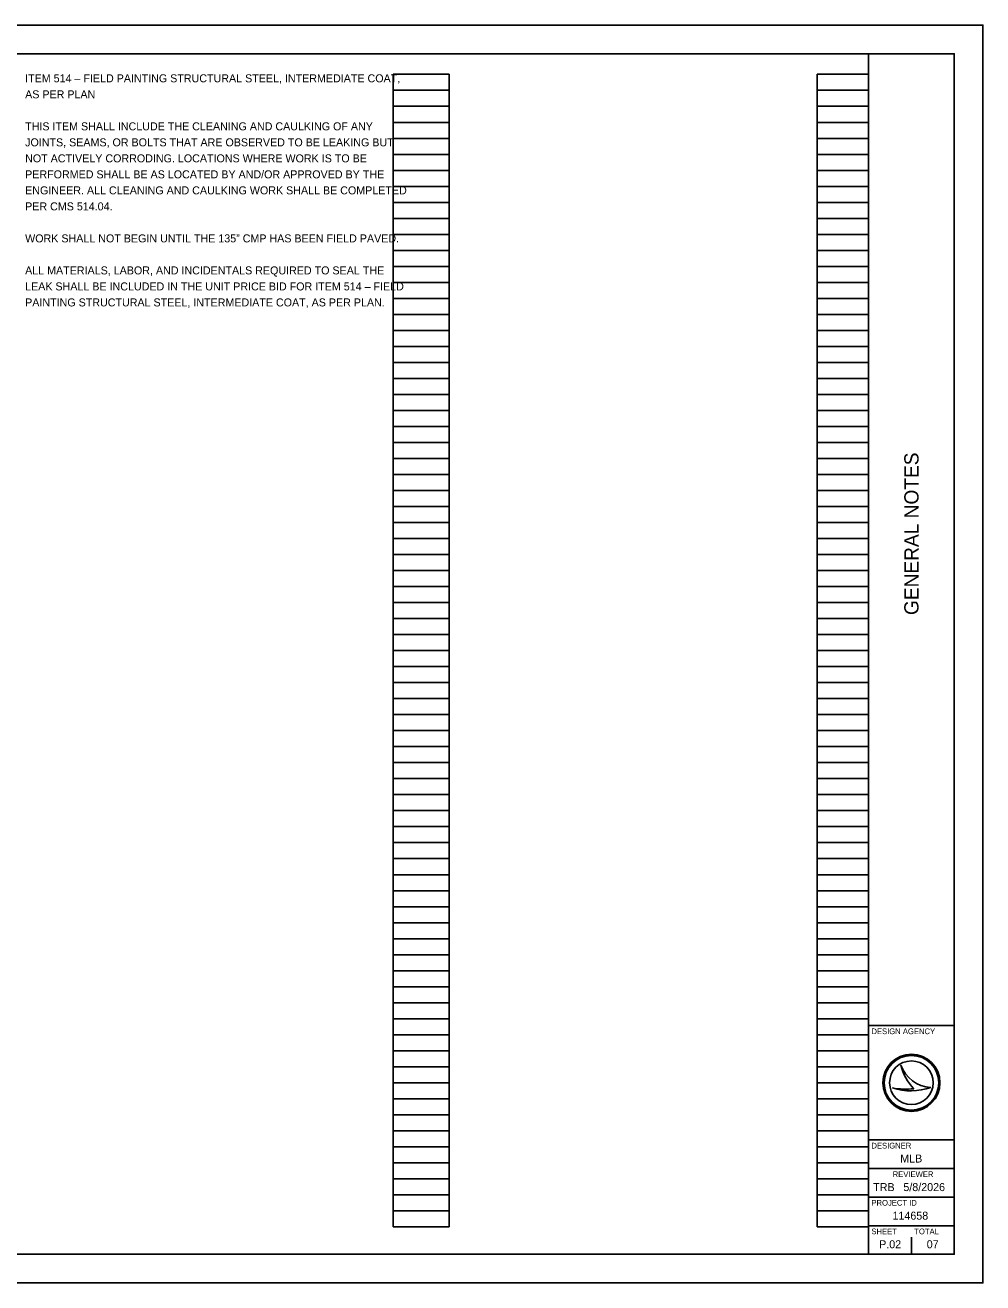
# Model space of a CAD drawing. Extents: x 0 to 34, y 0 to 22.
# Drawn here: x 17.24 to 34, y 0 to 22 of the extents above; entities that cross this region are included whole.
import ezdxf

# ---------------------------------------------------------------- set-up
doc = ezdxf.new("R2010")
doc.units = 0
for name, color, linetype in [('SH_Border', 7, 'Continuous'), ('SH_Cut_Line', 7, 'Continuous'), ('SH_Data', 7, 'Continuous'), ('SH_Text', 7, 'Continuous')]:
    doc.layers.add(name, color=color, linetype=linetype)

msp = doc.modelspace()

# ---------------------------------------------------------------- linework, layer by layer
at = {"layer": 'SH_Border'}
for p, q in [((32, 0.5), (32, 21.5)), ((32, 4.5), (33.5, 4.5)), ((32, 2.5), (33.5, 2.5)), ((32, 2), (33.5, 2)), ((32, 1.5), (33.5, 1.5)), ((32, 1), (33.5, 1))]:
    msp.add_line(p, q, dxfattribs=at)
msp.add_lwpolyline([(1.5, 21.5), (33.5, 21.5), (33.5, 0.5), (1.5, 0.5)], close=True, dxfattribs=at)
at = {"layer": 'SH_Cut_Line'}
msp.add_lwpolyline([(0, 0), (34, 0), (34, 22), (0, 22)], close=True, dxfattribs=at)
at = {"layer": 'SH_Data'}
for p, q in [((23.68, 0.98), (23.68, 21.14)), ((23.68, 21.14), (24.66, 21.14)), ((24.66, 0.98), (24.66, 21.14)), ((31.1, 0.98), (31.1, 21.14)), ((31.1, 21.14), (32, 21.14)), ((32, 0.98), (32, 21.14)), ((23.68, 20.86), (24.66, 20.86)), ((31.1, 20.86), (32, 20.86)), ((23.68, 20.58), (24.66, 20.58)), ((31.1, 20.58), (32, 20.58)), ((23.68, 20.3), (24.66, 20.3)), ((31.1, 20.3), (32, 20.3)), ((23.68, 20.02), (24.66, 20.02)), ((31.1, 20.02), (32, 20.02)), ((23.68, 19.74), (24.66, 19.74)), ((31.1, 19.74), (32, 19.74)), ((23.68, 19.46), (24.66, 19.46)), ((31.1, 19.46), (32, 19.46)), ((23.68, 19.18), (24.66, 19.18)), ((31.1, 19.18), (32, 19.18)), ((23.68, 18.9), (24.66, 18.9)), ((31.1, 18.9), (32, 18.9)), ((23.68, 18.62), (24.66, 18.62)), ((31.1, 18.62), (32, 18.62)), ((23.68, 18.34), (24.66, 18.34)), ((31.1, 18.34), (32, 18.34)), ((23.68, 18.06), (24.66, 18.06)), ((31.1, 18.06), (32, 18.06)), ((23.68, 17.78), (24.66, 17.78)), ((31.1, 17.78), (32, 17.78)), ((23.68, 17.5), (24.66, 17.5)), ((31.1, 17.5), (32, 17.5)), ((23.68, 17.22), (24.66, 17.22)), ((31.1, 17.22), (32, 17.22)), ((23.68, 16.94), (24.66, 16.94)), ((31.1, 16.94), (32, 16.94)), ((23.68, 16.66), (24.66, 16.66)), ((31.1, 16.66), (32, 16.66)), ((23.68, 16.38), (24.66, 16.38)), ((31.1, 16.38), (32, 16.38)), ((23.68, 16.1), (24.66, 16.1)), ((31.1, 16.1), (32, 16.1)), ((23.68, 15.82), (24.66, 15.82)), ((31.1, 15.82), (32, 15.82)), ((23.68, 15.54), (24.66, 15.54)), ((31.1, 15.54), (32, 15.54)), ((23.68, 15.26), (24.66, 15.26)), ((31.1, 15.26), (32, 15.26)), ((23.68, 14.98), (24.66, 14.98)), ((31.1, 14.98), (32, 14.98)), ((23.68, 14.7), (24.66, 14.7)), ((31.1, 14.7), (32, 14.7)), ((23.68, 14.42), (24.66, 14.42)), ((31.1, 14.42), (32, 14.42)), ((23.68, 14.14), (24.66, 14.14)), ((31.1, 14.14), (32, 14.14)), ((23.68, 13.86), (24.66, 13.86)), ((31.1, 13.86), (32, 13.86)), ((23.68, 13.58), (24.66, 13.58)), ((31.1, 13.58), (32, 13.58)), ((23.68, 13.3), (24.66, 13.3)), ((31.1, 13.3), (32, 13.3)), ((23.68, 13.02), (24.66, 13.02)), ((31.1, 13.02), (32, 13.02)), ((23.68, 12.74), (24.66, 12.74)), ((31.1, 12.74), (32, 12.74)), ((23.68, 12.46), (24.66, 12.46)), ((31.1, 12.46), (32, 12.46)), ((23.68, 12.18), (24.66, 12.18)), ((31.1, 12.18), (32, 12.18)), ((23.68, 11.9), (24.66, 11.9)), ((31.1, 11.9), (32, 11.9)), ((23.68, 11.62), (24.66, 11.62)), ((31.1, 11.62), (32, 11.62)), ((23.68, 11.34), (24.66, 11.34)), ((31.1, 11.34), (32, 11.34)), ((23.68, 11.06), (24.66, 11.06)), ((31.1, 11.06), (32, 11.06)), ((23.68, 10.78), (24.66, 10.78)), ((31.1, 10.78), (32, 10.78)), ((23.68, 10.5), (24.66, 10.5)), ((31.1, 10.5), (32, 10.5)), ((23.68, 10.22), (24.66, 10.22)), ((31.1, 10.22), (32, 10.22)), ((23.68, 9.94), (24.66, 9.94)), ((31.1, 9.94), (32, 9.94)), ((23.68, 9.66), (24.66, 9.66)), ((31.1, 9.66), (32, 9.66)), ((23.68, 9.38), (24.66, 9.38)), ((31.1, 9.38), (32, 9.38)), ((23.68, 9.1), (24.66, 9.1)), ((31.1, 9.1), (32, 9.1)), ((23.68, 8.82), (24.66, 8.82)), ((31.1, 8.82), (32, 8.82)), ((23.68, 8.54), (24.66, 8.54)), ((31.1, 8.54), (32, 8.54)), ((23.68, 8.26), (24.66, 8.26)), ((31.1, 8.26), (32, 8.26)), ((23.68, 7.98), (24.66, 7.98)), ((31.1, 7.98), (32, 7.98)), ((23.68, 7.7), (24.66, 7.7)), ((31.1, 7.7), (32, 7.7)), ((23.68, 7.42), (24.66, 7.42)), ((31.1, 7.42), (32, 7.42)), ((23.68, 7.14), (24.66, 7.14)), ((31.1, 7.14), (32, 7.14)), ((23.68, 6.86), (24.66, 6.86)), ((31.1, 6.86), (32, 6.86)), ((23.68, 6.58), (24.66, 6.58)), ((31.1, 6.58), (32, 6.58)), ((23.68, 6.3), (24.66, 6.3)), ((31.1, 6.3), (32, 6.3)), ((23.68, 6.02), (24.66, 6.02)), ((31.1, 6.02), (32, 6.02)), ((23.68, 5.74), (24.66, 5.74)), ((31.1, 5.74), (32, 5.74)), ((23.68, 5.46), (24.66, 5.46)), ((31.1, 5.46), (32, 5.46)), ((23.68, 5.18), (24.66, 5.18)), ((31.1, 5.18), (32, 5.18)), ((23.68, 4.9), (24.66, 4.9)), ((31.1, 4.9), (32, 4.9)), ((23.68, 4.62), (24.66, 4.62)), ((31.1, 4.62), (32, 4.62)), ((23.68, 4.34), (24.66, 4.34)), ((31.1, 4.34), (32, 4.34)), ((23.68, 4.06), (24.66, 4.06)), ((31.1, 4.06), (32, 4.06)), ((23.68, 3.78), (24.66, 3.78)), ((31.1, 3.78), (32, 3.78)), ((32.567, 3.81), (32.567, 3.81)), ((23.68, 3.5), (24.66, 3.5)), ((31.1, 3.5), (32, 3.5)), ((32.417, 3.41), (32.417, 3.41)), ((32.75, 3.5), (32.75, 3.5)), ((33.087, 3.419), (33.087, 3.419)), ((23.68, 3.22), (24.66, 3.22)), ((31.1, 3.22), (32, 3.22)), ((23.68, 2.94), (24.66, 2.94)), ((31.1, 2.94), (32, 2.94)), ((23.68, 2.66), (24.66, 2.66)), ((31.1, 2.66), (32, 2.66)), ((23.68, 2.38), (24.66, 2.38)), ((31.1, 2.38), (32, 2.38)), ((23.68, 2.1), (24.66, 2.1)), ((31.1, 2.1), (32, 2.1)), ((23.68, 1.82), (24.66, 1.82)), ((31.1, 1.82), (32, 1.82)), ((23.68, 1.54), (24.66, 1.54)), ((31.1, 1.54), (32, 1.54)), ((23.68, 1.26), (24.66, 1.26)), ((31.1, 1.26), (32, 1.26)), ((23.68, 0.98), (24.66, 0.98)), ((31.1, 0.98), (32, 0.98)), ((32.375, 0.675), (32.375, 0.675)), ((32.75, 0.5), (32.75, 0.8))]:
    msp.add_line(p, q, dxfattribs=at)
for radius in [0.5, 0.477, 0.477, 0.382]:
    msp.add_circle((32.75, 3.5), radius, dxfattribs=at)
for centre, radius, start, end in [((33.116, 3.998), 0.58, 198.9257, 198.9319), ((33.347, 3.97), 0.796, 191.6379, 191.6421), ((33.116, 3.998), 0.58, 198.9319, 267.1657), ((33.347, 3.97), 0.796, 191.6421, 226.0947), ((32.739, 4.37), 1.013, 251.4576, 290.0832), ((32.648, 4.654), 1.266, 259.4964, 259.4995), ((32.739, 4.37), 1.013, 251.4527, 251.4576), ((32.648, 4.654), 1.266, 259.4995, 276.6672)]:
    msp.add_arc(centre, radius, start, end, dxfattribs=at)

# ---------------------------------------------------------------- texts
msp.add_text('GENERAL NOTES', height=0.25, rotation=90, dxfattribs=at).set_placement((32.875, 11.682))
for s, height, p in [('DESIGN AGENCY', 0.1, (32.05, 4.35)), ('DESIGNER', 0.1, (32.05, 2.35)), ('MLB', 0.14, (32.554, 2.105)), ('REVIEWER', 0.1, (32.422, 1.85)), ('TRB', 0.14, (32.081, 1.605)), ('5/8/2026', 0.14, (32.609, 1.605)), ('PROJECT ID', 0.1, (32.05, 1.35)), ('114658', 0.14, (32.419, 1.105)), ('SHEET', 0.1, (32.05, 0.85)), ('TOTAL', 0.1, (32.8, 0.85)), ('P.02', 0.14, (32.185, 0.605)), ('07', 0.14, (33.018, 0.605))]:
    msp.add_text(s, height=height, dxfattribs=at).set_placement(p)
at = {"layer": 'SH_Text'}
for s, p in [('ITEM 514 – FIELD PAINTING STRUCTURAL STEEL, INTERMEDIATE COAT, ', (17.24, 21)), ('AS PER PLAN', (17.24, 20.72)), ('THIS ITEM SHALL INCLUDE THE CLEANING AND CAULKING OF ANY ', (17.24, 20.16)), ('JOINTS, SEAMS, OR BOLTS THAT ARE OBSERVED TO BE LEAKING BUT ', (17.24, 19.88)), ('NOT ACTIVELY CORRODING. LOCATIONS WHERE WORK IS TO BE ', (17.24, 19.6)), ('PERFORMED SHALL BE AS LOCATED BY AND/OR APPROVED BY THE ', (17.24, 19.32)), ('ENGINEER. ALL CLEANING AND CAULKING WORK SHALL BE COMPLETED ', (17.24, 19.04)), ('PER CMS 514.04.  ', (17.24, 18.76)), ('WORK SHALL NOT BEGIN UNTIL THE 135” CMP HAS BEEN FIELD PAVED.', (17.24, 18.2)), ('ALL MATERIALS, LABOR, AND INCIDENTALS REQUIRED TO SEAL THE ', (17.24, 17.64)), ('LEAK SHALL BE INCLUDED IN THE UNIT PRICE BID FOR ITEM 514 – FIELD ', (17.24, 17.36)), ('PAINTING STRUCTURAL STEEL, INTERMEDIATE COAT, AS PER PLAN.', (17.24, 17.08))]:
    msp.add_text(s, height=0.14, dxfattribs=at).set_placement(p)

doc.saveas('drawing.dxf')
